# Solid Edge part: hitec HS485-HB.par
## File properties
Last saved by: nakano
Revision: 75
Density: 1420.92818846485 kg/m^3
Accuracy: 0.990
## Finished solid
Body 1: solid body, 167 faces, 436 edges, 276 vertices.
  Faces by surface: plane 109, cylinder 42, cone 16
  Edges by curve: line 324, circle 112
Bounding box of the edges (mm): 19.810 x 52.980 x 39.740, from (31.8933, 32.9402, 0) to (51.7033, 85.9202, 39.74).
Cylindrical faces by radius (mm): R0.15 x4, R1 x4, R1.3237 x4, R1.5 x1, R2 x16, R2.25 x4, R2.5 x4, R2.75 x1, R5 x1, R6 x1, R7 x1, R9.515 x1
Conical faces (half-angle, radius in mm at the cone's reference point): 60 deg R1.9567 x8, 60 deg R2 x8
Planar faces by outward normal: +x 17, +y 15, +z 16, -x 17, -y 13, -z 9, oblique 22
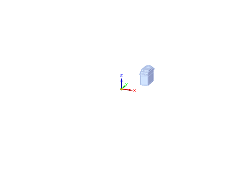
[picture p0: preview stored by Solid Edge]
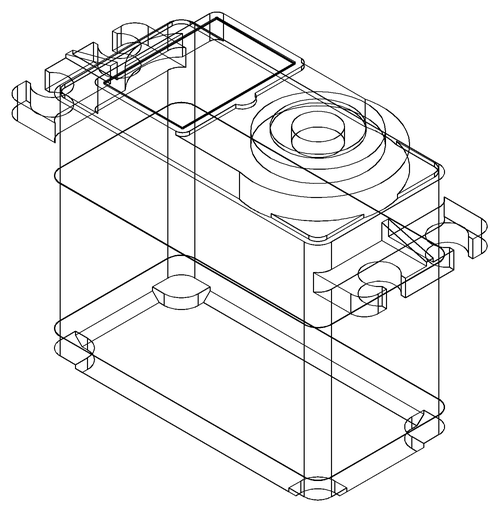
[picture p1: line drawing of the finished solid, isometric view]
